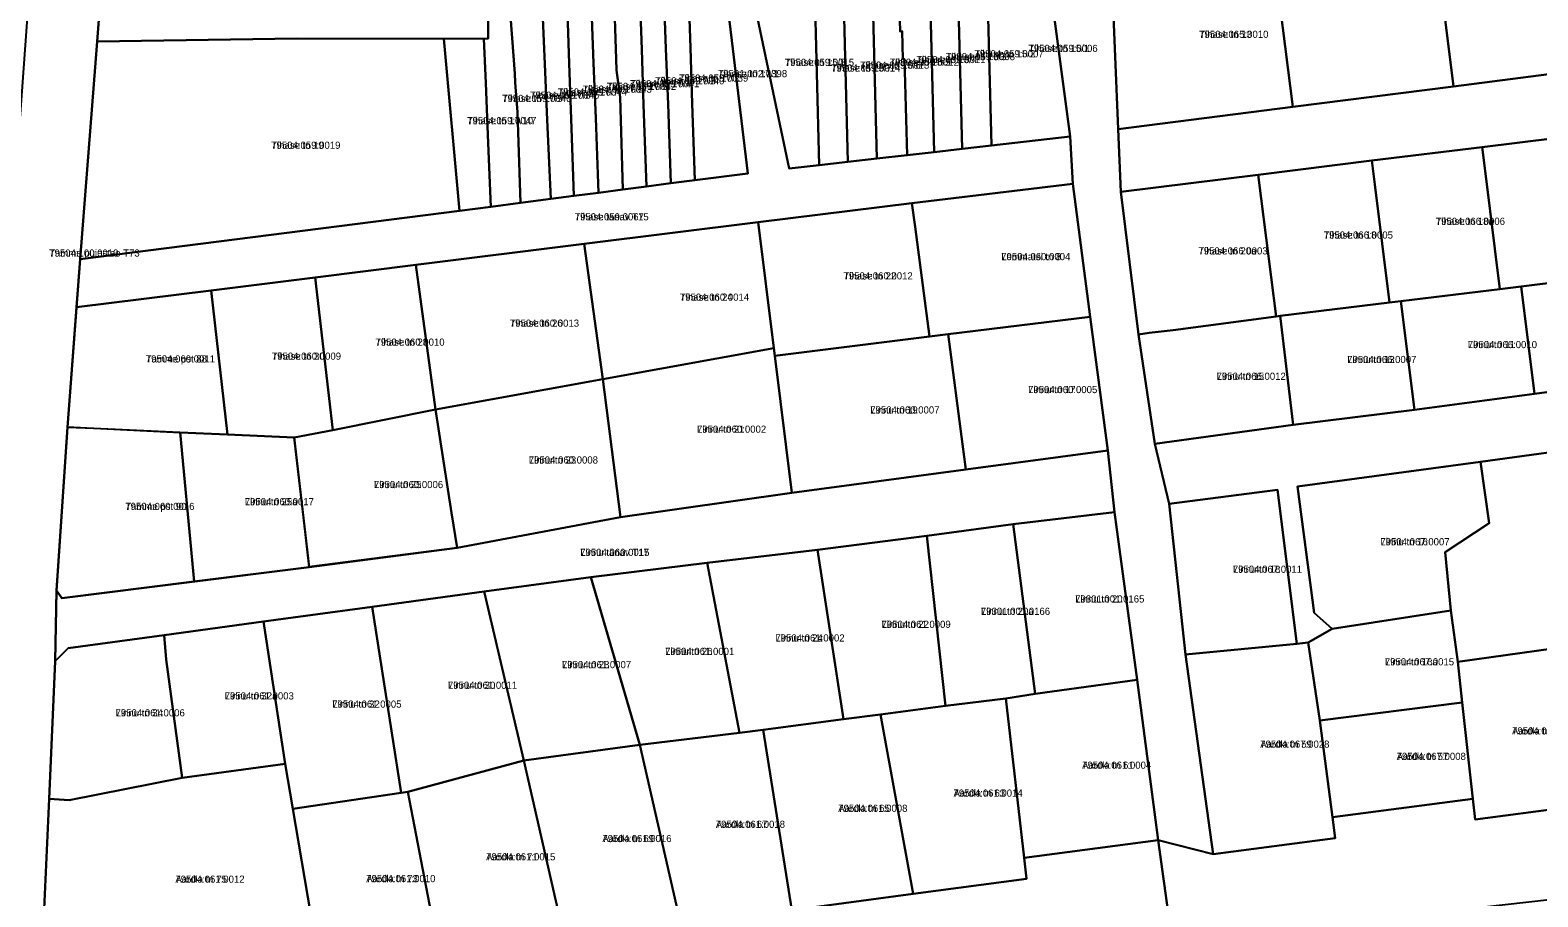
# Model space of a CAD drawing. Extents: x 643847 to 663718, y 6468443 to 6482775.
# Drawn here: x 657831.9 to 658147.9, y 6471388.2 to 6471569.9 of the extents above; entities that cross this region are included whole.
import ezdxf

# ---------------------------------------------------------------- set-up
doc = ezdxf.new("R2010")
doc.units = 0
for name, color, linetype in [('L_AADRESS', 7, 'Continuous'), ('PIIR', 7, 'Continuous'), ('TUNNUS', 7, 'Continuous')]:
    doc.layers.add(name, color=color, linetype=linetype)

msp = doc.modelspace()

# ---------------------------------------------------------------- linework, layer by layer
at = {"layer": 'PIIR'}
for points in [[(658130.25, 6471558.12), (658126.07, 6471591.82), (658156.31, 6471595.73), (658160.5, 6471561.99)], [(658292.42, 6471578.15), (658365.6, 6471587.41), (658367.83, 6471590.26), (658373.75, 6471575.36), (658352.14, 6471572.67), (658318.73, 6471568.44), (658286.02, 6471564.29), (658253.03, 6471560.11), (658242.37, 6471558.76), (658234.14, 6471557.53), (658205.59, 6471553.99), (658182.49, 6471551.12), (658159.39, 6471548.25), (658136.28, 6471545.4), (658113.15, 6471542.55), (658089.33, 6471539.59), (658060.55, 6471536.03), (658060, 6471549.15), (658096.63, 6471553.82), (658130.25, 6471558.12), (658160.5, 6471561.99), (658192.51, 6471566.07), (658224.48, 6471569.95), (658262.69, 6471574.19)], [(658096.63, 6471553.82), (658092.3, 6471587.44), (658126.07, 6471591.82), (658130.25, 6471558.12)], [(657847.52, 6471587.53), (657887.77, 6471587.84), (657911.97, 6471588.03), (657919.5, 6471588.11), (657925.57, 6471588.16), (657927.77, 6471588.18), (657927.88, 6471576.18), (657927.93, 6471568.15), (657918.62, 6471568.07), (657887.92, 6471568.15), (657845.97, 6471567.52)], [(658060, 6471549.15), (658058.59, 6471583.07), (658092.3, 6471587.44), (658096.63, 6471553.82)], [(658049.93, 6471547.63), (658033.46, 6471545.74), (658032.45, 6471583.31), (658042.89, 6471584.19), (658044.85, 6471585.99)], [(657977.44, 6471581.18), (657982.36, 6471539.86), (657971.24, 6471538.44), (657970.71, 6471554.54), (657970.34, 6471566.19), (657969.87, 6471580.42)], [(658003.34, 6471542.29), (657997.29, 6471541.6), (657996.33, 6471580.28), (658002.38, 6471580.79)], [(658009.39, 6471542.98), (658003.34, 6471542.29), (658002.38, 6471580.79), (658008.44, 6471581.3)], [(658014.31, 6471569.62), (658014.74, 6471569.7), (658014.89, 6471563.86), (658015.23, 6471563.86), (658015.79, 6471543.72), (658009.39, 6471542.98), (658008.44, 6471581.3), (658013.93, 6471581.76)], [(658021.43, 6471544.36), (658015.79, 6471543.72), (658015.23, 6471563.86), (658014.89, 6471563.86), (658014.74, 6471569.7), (658014.31, 6471569.62), (658013.93, 6471581.76), (658020.41, 6471582.3)], [(658027.32, 6471545.04), (658021.43, 6471544.36), (658020.41, 6471582.3), (658026.3, 6471582.8)], [(658033.46, 6471545.74), (658027.32, 6471545.04), (658026.3, 6471582.8), (658032.45, 6471583.31)], [(657934.71, 6471533.72), (657934.25, 6471548.5), (657934.12, 6471552.73), (657933.59, 6471558.94), (657933.53, 6471560.83), (657932.37, 6471576.63), (657937.59, 6471577.17), (657939.22, 6471577.33), (657939.83, 6471562.76), (657940.32, 6471551.12), (657941.09, 6471534.53)], [(657941.09, 6471534.53), (657940.32, 6471551.12), (657939.83, 6471562.76), (657939.22, 6471577.33), (657943.65, 6471577.78), (657944.43, 6471577.85), (657944.94, 6471562.89), (657945.33, 6471551.29), (657945.87, 6471535.17)], [(657945.87, 6471535.17), (657945.33, 6471551.29), (657944.94, 6471562.89), (657944.43, 6471577.85), (657949.47, 6471578.36), (657950.05, 6471563.01), (657950.48, 6471551.45), (657951.07, 6471535.83)], [(657951.07, 6471535.83), (657950.48, 6471551.45), (657950.05, 6471563.01), (657949.47, 6471578.36), (657949.69, 6471578.38), (657954.29, 6471578.84), (657954.78, 6471563.86), (657954.86, 6471561.53), (657955.64, 6471555.86), (657955.71, 6471553.4), (657956.2, 6471536.5)], [(657956.2, 6471536.5), (657955.71, 6471553.4), (657955.64, 6471555.86), (657954.86, 6471561.53), (657954.78, 6471563.86), (657954.29, 6471578.84), (657955.63, 6471578.99), (657959.66, 6471579.39), (657960.12, 6471565.83), (657960.52, 6471554.23), (657961.11, 6471537.13)], [(657961.11, 6471537.13), (657960.52, 6471554.23), (657960.12, 6471565.83), (657959.66, 6471579.39), (657961.92, 6471579.62), (657964.69, 6471579.9), (657965.21, 6471566.02), (657965.64, 6471554.39), (657966.25, 6471537.8)], [(657970.71, 6471554.54), (657971.24, 6471538.44), (657966.25, 6471537.8), (657965.64, 6471554.39), (657965.21, 6471566.02), (657964.69, 6471579.9), (657969.87, 6471580.42), (657970.34, 6471566.19)], [(657997.29, 6471541.6), (657991.02, 6471540.88), (657983, 6471579.16), (657996.33, 6471580.28)], [(657928.47, 6471532.9), (657927.94, 6471546.2), (657927.43, 6471558.77), (657927.05, 6471568.14), (657927.93, 6471568.15), (657927.88, 6471576.18), (657931.64, 6471576.56), (657932.37, 6471576.63), (657933.53, 6471560.83), (657933.59, 6471558.94), (657934.12, 6471552.73), (657934.25, 6471548.5), (657934.71, 6471533.72)], [(657842.41, 6471521.91), (657845.97, 6471567.52), (657887.92, 6471568.15), (657918.62, 6471568.07), (657921.93, 6471532.05)], [(657921.93, 6471532.05), (657918.62, 6471568.07), (657927.05, 6471568.14), (657927.43, 6471558.77), (657927.94, 6471546.2), (657928.47, 6471532.9)], [(658159.39, 6471548.25), (658160, 6471543.3), (658163.07, 6471518.49), (658144.44, 6471516.18), (658139.97, 6471515.63), (658136.89, 6471540.43), (658136.28, 6471545.4)], [(658113.15, 6471542.55), (658113.76, 6471537.58), (658116.83, 6471512.78), (658093.92, 6471510), (658093.08, 6471509.85), (658089.94, 6471534.64), (658089.33, 6471539.59)], [(658136.28, 6471545.4), (658136.89, 6471540.43), (658139.97, 6471515.63), (658119.26, 6471513.06), (658116.83, 6471512.78), (658113.76, 6471537.58), (658113.15, 6471542.55)], [(658060.55, 6471536.03), (658089.33, 6471539.59), (658089.94, 6471534.64), (658093.08, 6471509.85), (658071.52, 6471507.02), (658066.48, 6471506.48), (658064.28, 6471506.12)], [(658054.15, 6471509.83), (658024.39, 6471506.14), (658020.42, 6471505.65), (658017.41, 6471528.7), (658016.76, 6471533.66), (658050.52, 6471537.71)], [(658016.76, 6471533.66), (658017.41, 6471528.7), (658020.42, 6471505.65), (657988.01, 6471501.62), (657987.81, 6471503.21), (657984.52, 6471529.64)], [(657948.05, 6471525.11), (657984.52, 6471529.64), (657987.81, 6471503.21), (657951.99, 6471496.71)], [(657948.05, 6471525.11), (657951.99, 6471496.71), (657916.91, 6471490.35), (657912.77, 6471520.72)], [(657912.77, 6471520.72), (657916.91, 6471490.35), (657895.36, 6471486.07), (657891.71, 6471518.08)], [(657891.71, 6471518.08), (657895.36, 6471486.07), (657887.31, 6471484.47), (657873.33, 6471485.11), (657869.87, 6471515.34)], [(658144.44, 6471516.18), (658163.07, 6471518.49), (658170.24, 6471519.38), (658173.01, 6471497.13), (658147.25, 6471493.67)], [(657841.66, 6471511.8), (657869.87, 6471515.34), (657873.33, 6471485.11), (657863.34, 6471485.57), (657845.25, 6471486.41), (657839.77, 6471486.67)], [(658139.97, 6471515.63), (658144.44, 6471516.18), (658147.25, 6471493.67), (658122.08, 6471490.29), (658119.26, 6471513.06)], [(658116.83, 6471512.78), (658119.26, 6471513.06), (658122.08, 6471490.29), (658096.7, 6471487.16), (658093.92, 6471510)], [(658028.08, 6471477.78), (658027.39, 6471483.09), (658024.39, 6471506.14), (658054.15, 6471509.83), (658057.8, 6471481.75)], [(658093.08, 6471509.85), (658093.92, 6471510), (658096.7, 6471487.16), (658067.68, 6471483.18), (658064.28, 6471506.12), (658066.48, 6471506.48), (658071.52, 6471507.02)], [(657991.61, 6471472.92), (657988.01, 6471501.62), (658020.42, 6471505.65), (658024.39, 6471506.14), (658027.39, 6471483.09), (658028.08, 6471477.78)], [(657955.67, 6471467.79), (657951.99, 6471496.71), (657987.81, 6471503.21), (657988.01, 6471501.62), (657991.61, 6471472.92)], [(657921.43, 6471461.37), (657920.29, 6471468.69), (657916.91, 6471490.35), (657951.99, 6471496.71), (657955.67, 6471467.79)], [(657890.45, 6471457.42), (657889.59, 6471464.81), (657887.31, 6471484.47), (657895.36, 6471486.07), (657916.91, 6471490.35), (657920.29, 6471468.69), (657921.43, 6471461.37)], [(657866.3, 6471454.32), (657838.57, 6471450.83), (657837.49, 6471452.39), (657839.81, 6471486.69), (657845.29, 6471486.43), (657863.39, 6471485.56)], [(657890.46, 6471457.35), (657866.3, 6471454.32), (657863.39, 6471485.56), (657873.33, 6471485.11), (657887.31, 6471484.47)], [(658162.4, 6471483), (658165.04, 6471462.92), (658168.02, 6471441.42), (658151.17, 6471440.28), (658131.19, 6471437.48), (658129.72, 6471448.25), (658128.5, 6471460.49), (658137.75, 6471466.52), (658135.92, 6471479.41)], [(657991.61, 6471472.92), (658028.08, 6471477.78), (658057.8, 6471481.75), (658059.22, 6471468.86), (658038.01, 6471466.35), (658019.87, 6471463.91), (657996.99, 6471460.98), (657973.88, 6471458.19), (657949.45, 6471455.24), (657927.1, 6471452.18), (657903.64, 6471448.98), (657880.85, 6471445.9), (657860.01, 6471443.06), (657839.91, 6471440.31), (657837.22, 6471437.59), (657837.49, 6471452.39), (657838.57, 6471450.83), (657890.46, 6471457.35), (657921.43, 6471461.37), (657955.67, 6471467.79)], [(658135.92, 6471479.41), (658137.75, 6471466.52), (658128.5, 6471460.49), (658129.72, 6471448.25), (658104.86, 6471444.4), (658101.09, 6471447.77), (658097.59, 6471474.23)], [(658093.4, 6471473.55), (658097.41, 6471441.25), (658074.07, 6471438.97), (658070.66, 6471470.56)], [(658042.57, 6471430.75), (658038.01, 6471466.35), (658059.22, 6471468.86), (658063.95, 6471433.7)], [(658019.87, 6471463.91), (658023.79, 6471428.27), (658010.18, 6471426.44), (658002.42, 6471425.45), (657996.99, 6471460.98)], [(658023.79, 6471428.27), (658019.87, 6471463.91), (658038.01, 6471466.35), (658042.57, 6471430.75), (658036.45, 6471429.81)], [(657996.99, 6471460.98), (658002.42, 6471425.45), (657985.6, 6471423.21), (657980.6, 6471422.61), (657973.88, 6471458.19)], [(657973.88, 6471458.19), (657980.6, 6471422.61), (657959.71, 6471420.04), (657949.45, 6471455.24)], [(657949.45, 6471455.24), (657959.71, 6471420.04), (657935.41, 6471416.76), (657927.1, 6471452.18)], [(657903.64, 6471448.98), (657927.1, 6471452.18), (657935.41, 6471416.76), (657911.1, 6471410.21), (657909.7, 6471410)], [(657903.64, 6471448.98), (657909.7, 6471410), (657887.02, 6471406.64), (657885.43, 6471416.08), (657880.85, 6471445.9)], [(658129.72, 6471448.25), (658131.19, 6471437.48), (658132.07, 6471428.91), (658102.24, 6471425.2), (658099.79, 6471441.49), (658104.86, 6471444.4)], [(657880.85, 6471445.9), (657885.43, 6471416.08), (657863.78, 6471413.17), (657860.45, 6471437.94), (657860.01, 6471443.06)], [(657839.91, 6471440.31), (657860.01, 6471443.06), (657860.45, 6471437.94), (657863.78, 6471413.17), (657840.14, 6471408.44), (657835.93, 6471408.73), (657837.22, 6471437.59)], [(658079.89, 6471397.11), (658074.07, 6471438.97), (658097.41, 6471441.25), (658099.79, 6471441.49), (658102.24, 6471425.2), (658104.9, 6471404.89), (658105.48, 6471400.5)], [(658134.78, 6471404.38), (658134.3, 6471408.73), (658132.07, 6471428.91), (658131.19, 6471437.48), (658151.17, 6471440.28), (658153.53, 6471411.25), (658153.89, 6471406.9)], [(658068.39, 6471400.1), (658040.27, 6471396.4), (658036.45, 6471429.81), (658042.57, 6471430.75), (658063.95, 6471433.7)], [(658017.04, 6471388.8), (658010.18, 6471426.44), (658023.79, 6471428.27), (658036.45, 6471429.81), (658040.27, 6471396.4), (658040.78, 6471391.94)], [(658104.9, 6471404.89), (658102.24, 6471425.2), (658132.07, 6471428.91), (658134.3, 6471408.73)], [(657991.61, 6471385.43), (657985.6, 6471423.21), (658002.42, 6471425.45), (658010.18, 6471426.44), (658017.04, 6471388.8)], [(657991.61, 6471385.43), (657968.36, 6471382.36), (657959.71, 6471420.04), (657980.6, 6471422.61), (657985.6, 6471423.21)], [(657943.94, 6471379.4), (657935.41, 6471416.76), (657959.71, 6471420.04), (657968.36, 6471382.36)], [(657917.76, 6471375.66), (657911.1, 6471410.21), (657935.41, 6471416.76), (657943.94, 6471379.4)], [(657846.48, 6471366.23), (657844.25, 6471382.89), (657834.76, 6471382.58), (657835.93, 6471408.73), (657840.14, 6471408.44), (657863.78, 6471413.17), (657885.43, 6471416.08), (657887.02, 6471406.64), (657892.03, 6471377.02), (657892.82, 6471372.36)], [(657892.82, 6471372.36), (657892.03, 6471377.02), (657887.02, 6471406.64), (657909.7, 6471410), (657911.1, 6471410.21), (657917.76, 6471375.66)], [(658040.27, 6471396.4), (658068.39, 6471400.1), (658071.44, 6471377.84), (658040.7, 6471373.77), (658015, 6471369.11), (657981.76, 6471364.87), (657955.06, 6471361.46), (657930.15, 6471359.24), (657869.84, 6471351.31), (657832.75, 6471346.26), (657833.95, 6471364.57), (657846.48, 6471366.23), (657892.82, 6471372.36), (657917.76, 6471375.66), (657943.94, 6471379.4), (657968.36, 6471382.36), (657991.61, 6471385.43), (658017.04, 6471388.8), (658040.78, 6471391.94)]]:
    msp.add_lwpolyline(points, close=True, dxfattribs=at)
for points in [[(657847.52, 6471587.53), (657845.97, 6471567.52), (657842.41, 6471521.91), (657839.77, 6471486.67), (657837.5, 6471452.36), (657837.22, 6471437.59), (657835.93, 6471408.73), (657834.76, 6471382.58), (657833.95, 6471364.57), (657832.75, 6471346.26), (657818.06, 6471342.66), (657815.82, 6471355.91), (657818.38, 6471384.03), (657820.03, 6471406.57), (657821.19, 6471434.16), (657823.07, 6471447.88), (657824.85, 6471478.3), (657827.44, 6471517.38), (657828.11, 6471527.43), (657829.93, 6471552.31), (657832.8, 6471591.95)], [(658058.59, 6471583.07), (658060, 6471549.15), (658060.55, 6471536.03), (658064.28, 6471506.12), (658067.68, 6471483.18), (658070.66, 6471470.56), (658074.07, 6471438.97), (658079.89, 6471397.11), (658068.39, 6471400.1), (658063.95, 6471433.7), (658059.22, 6471468.86), (658057.8, 6471481.75), (658054.15, 6471509.83), (658050.52, 6471537.71), (658049.93, 6471547.63), (658044.85, 6471585.99)], [(657983, 6471579.16), (657991.02, 6471540.88), (657997.29, 6471541.6), (658003.34, 6471542.29), (658009.39, 6471542.98), (658015.79, 6471543.72), (658021.43, 6471544.36), (658027.32, 6471545.04), (658033.46, 6471545.74), (658049.93, 6471547.63), (658050.52, 6471537.71), (658016.76, 6471533.66), (657984.52, 6471529.64), (657948.05, 6471525.11), (657912.77, 6471520.72), (657891.71, 6471518.08), (657869.87, 6471515.34), (657841.66, 6471511.8), (657842.41, 6471521.91), (657921.93, 6471532.05), (657928.47, 6471532.9), (657934.71, 6471533.72), (657941.09, 6471534.53), (657945.87, 6471535.17), (657951.07, 6471535.83), (657956.2, 6471536.5), (657961.11, 6471537.13), (657966.25, 6471537.8), (657971.24, 6471538.44), (657982.36, 6471539.86), (657977.44, 6471581.18)], [(658162.4, 6471483), (658135.92, 6471479.41), (658097.59, 6471474.23), (658101.09, 6471447.77), (658104.86, 6471444.4), (658099.79, 6471441.49), (658097.41, 6471441.25), (658093.4, 6471473.55), (658070.66, 6471470.56), (658067.68, 6471483.18), (658096.7, 6471487.16), (658122.08, 6471490.29), (658147.25, 6471493.67), (658173.01, 6471497.13)], [(658150.36, 6471387.58), (658118.18, 6471383.93), (658080.99, 6471379.35), (658071.44, 6471377.84), (658068.39, 6471400.1), (658079.89, 6471397.11), (658105.48, 6471400.5), (658104.9, 6471404.89), (658134.3, 6471408.73), (658134.78, 6471404.38), (658153.89, 6471406.9)]]:
    msp.add_lwpolyline(points, dxfattribs=at)

# ---------------------------------------------------------------- texts
at = {"layer": 'L_AADRESS'}
for s, p in [('Tihase tn 13', (658076.98, 6471568.29)), ('Tihase tn 15/3', (658023.86, 6471563.62)), ('Tihase tn 15/2', (658029.88, 6471564.21)), ('Tihase tn 15/1', (658041.19, 6471565.34)), ('Tihase tn 17/1', (657976.11, 6471560.05)), ('Tihase tn 15/8', (657990.14, 6471562.41)), ('Tihase tn 15/7', (657999.84, 6471561.23)), ('Tihase tn 15/6', (658005.89, 6471561.83)), ('Tihase tn 15/5', (658012.11, 6471562.45)), ('Tihase tn 15/4', (658017.68, 6471563)), ('Tihase tn 17/6', (657947.75, 6471556.8)), ('Tihase tn 17/5', (657952.84, 6471557.38)), ('Tihase tn 17/4', (657957.7, 6471557.94)), ('Tihase tn 17/3', (657962.95, 6471558.55)), ('Tihase tn 17/2', (657967.96, 6471559.12)), ('Tihase tn 17/9', (657930.88, 6471554.85)), ('Tihase tn 17/8', (657936.73, 6471555.53)), ('Tihase tn 17/7', (657942.54, 6471556.2)), ('Tihase tn 17/10', (657923.54, 6471550.19)), ('Tihase tn 19', (657882.48, 6471545.03)), ('Tihase tänav T15', (657946.09, 6471530.03)), ('Tihase tn 18a', (658126.56, 6471529.08)), ('Tihase tn 18', (658103.08, 6471526.21)), ('Tamme puiestee T73', (657835.95, 6471522.43)), ('Tihase tn 20a', (658076.81, 6471522.88)), ('Lemmatsi tn 8', (658035.47, 6471521.68)), ('Tihase tn 22', (658002.43, 6471517.64)), ('Tihase tn 24', (657968.14, 6471513.18)), ('Tihase tn 26', (657932.5, 6471507.73)), ('Tihase tn 28', (657904.31, 6471503.75)), ('Linnu tn 11', (658133.27, 6471503.24)), ('Tamme pst 88', (657856.19, 6471500.23)), ('Tihase tn 30', (657882.61, 6471500.81)), ('Linnu tn 13', (658107.99, 6471500.11)), ('Linnu tn 17', (658041.11, 6471493.8)), ('Linnu tn 15', (658080.62, 6471496.59)), ('Linnu tn 19', (658008.04, 6471489.53)), ('Linnu tn 21', (657971.72, 6471485.5)), ('Linnu tn 23', (657936.46, 6471479.04)), ('Linnu tn 25', (657904.01, 6471473.89)), ('Tamme pst 90', (657851.89, 6471469.31)), ('Linnu tn 25a', (657876.93, 6471470.3)), ('Linnu tänav T17', (657947.24, 6471459.67)), ('Linnu tn 16', (658114.95, 6471461.9)), ('Linnu tn 18', (658084.03, 6471456.13)), ('Linnu tn 20', (658050.98, 6471449.9)), ('Linnu tn 20a', (658031.22, 6471447.31)), ('Linnu tn 22', (658010.39, 6471444.58)), ('Linnu tn 24', (657988.15, 6471441.73)), ('Linnu tn 26', (657965.03, 6471438.91)), ('Linnu tn 16a', (658115.89, 6471436.73)), ('Linnu tn 28', (657943.41, 6471436.13)), ('Linnu tn 30', (657919.52, 6471431.81)), ('Linnu tn 32a', (657872.72, 6471429.58)), ('Linnu tn 32', (657895.28, 6471427.86)), ('Linnu tn 34', (657849.86, 6471426.03)), ('Aardla tn 55a', (658142.54, 6471422.24)), ('Aardla tn 59', (658089.77, 6471419.46)), ('Aardla tn 61', (658052.42, 6471415.05)), ('Aardla tn 57', (658118.36, 6471416.9)), ('Aardla tn 63', (658025.48, 6471409.2)), ('Aardla tn 65', (658001.32, 6471406.01)), ('Aardla tn 67', (657975.66, 6471402.66)), ('Aardla tn 69', (657951.88, 6471399.67)), ('Aardla tn 71', (657927.52, 6471395.84)), ('Aardla tn 75', (657862.39, 6471391.15)), ('Aardla tn 73', (657902.39, 6471391.27))]:
    msp.add_text(s, height=1.5, dxfattribs=at).set_placement(p)
at = {"layer": 'TUNNUS'}
for s, p in [('79504:065:0010', (658076.98, 6471568.29)), ('79504:059:0008', (658023.86, 6471563.62)), ('79504:059:0007', (658029.88, 6471564.21)), ('79504:059:0006', (658041.19, 6471565.34)), ('79501:002:0398', (657976.11, 6471560.05)), ('79504:059:0015', (657990.14, 6471562.41)), ('79504:059:0014', (657999.84, 6471561.23)), ('79504:059:0013', (658005.89, 6471561.83)), ('79504:059:0012', (658012.11, 6471562.45)), ('79504:059:0011', (658017.68, 6471563)), ('79504:059:0042', (657952.84, 6471557.38)), ('79504:059:0041', (657957.7, 6471557.94)), ('79504:059:0040', (657962.95, 6471558.55)), ('79504:059:0039', (657967.96, 6471559.12)), ('79504:059:0046', (657930.88, 6471554.85)), ('79504:059:0045', (657936.73, 6471555.53)), ('79504:059:0044', (657942.54, 6471556.2)), ('79504:059:0043', (657947.75, 6471556.8)), ('79504:059:0047', (657923.54, 6471550.19)), ('79504:059:0019', (657882.48, 6471545.03)), ('79504:059:0067', (657946.09, 6471530.03)), ('79504:066:0006', (658126.56, 6471529.08)), ('79504:066:0005', (658103.08, 6471526.21)), ('79504:100:0010', (657835.95, 6471522.43)), ('79504:066:0003', (658076.81, 6471522.88)), ('79504:060:0004', (658035.47, 6471521.68)), ('79504:060:0012', (658002.43, 6471517.64)), ('79504:060:0014', (657968.14, 6471513.18)), ('79504:060:0013', (657932.5, 6471507.73)), ('79504:060:0010', (657904.31, 6471503.75)), ('79504:066:0010', (658133.27, 6471503.24)), ('79504:060:0011', (657856.19, 6471500.23)), ('79504:060:0009', (657882.61, 6471500.81)), ('79504:066:0007', (658107.99, 6471500.11)), ('79504:060:0005', (658041.11, 6471493.8)), ('79504:066:0012', (658080.62, 6471496.59)), ('79504:060:0007', (658008.04, 6471489.53)), ('79504:060:0002', (657971.72, 6471485.5)), ('79504:060:0008', (657936.46, 6471479.04)), ('79504:060:0006', (657904.01, 6471473.89)), ('79504:060:0016', (657851.89, 6471469.31)), ('79504:060:0017', (657876.93, 6471470.3)), ('79504:060:0015', (657947.24, 6471459.67)), ('79504:067:0007', (658114.95, 6471461.9)), ('79504:067:0011', (658084.03, 6471456.13)), ('79301:001:0165', (658050.98, 6471449.9)), ('79301:001:0166', (658031.22, 6471447.31)), ('79504:061:0009', (658010.39, 6471444.58)), ('79504:061:0002', (657988.15, 6471441.73)), ('79504:061:0001', (657965.03, 6471438.91)), ('79504:061:0007', (657943.41, 6471436.13)), ('79504:067:0015', (658115.89, 6471436.73)), ('79504:061:0011', (657919.52, 6471431.81)), ('79504:061:0003', (657872.72, 6471429.58)), ('79504:061:0005', (657895.28, 6471427.86)), ('79504:061:0006', (657849.86, 6471426.03)), ('79504:067:0026', (658142.54, 6471422.24)), ('79504:067:0028', (658089.77, 6471419.46)), ('79504:061:0004', (658052.42, 6471415.05)), ('79504:067:0008', (658118.36, 6471416.9)), ('79504:061:0014', (658025.48, 6471409.2)), ('79504:061:0008', (658001.32, 6471406.01)), ('79504:061:0018', (657975.66, 6471402.66)), ('79504:061:0016', (657951.88, 6471399.67)), ('79504:061:0015', (657927.52, 6471395.84)), ('79504:061:0012', (657862.39, 6471391.15)), ('79504:061:0010', (657902.39, 6471391.27))]:
    msp.add_text(s, height=1.5, dxfattribs=at).set_placement(p)

doc.saveas('drawing.dxf')
